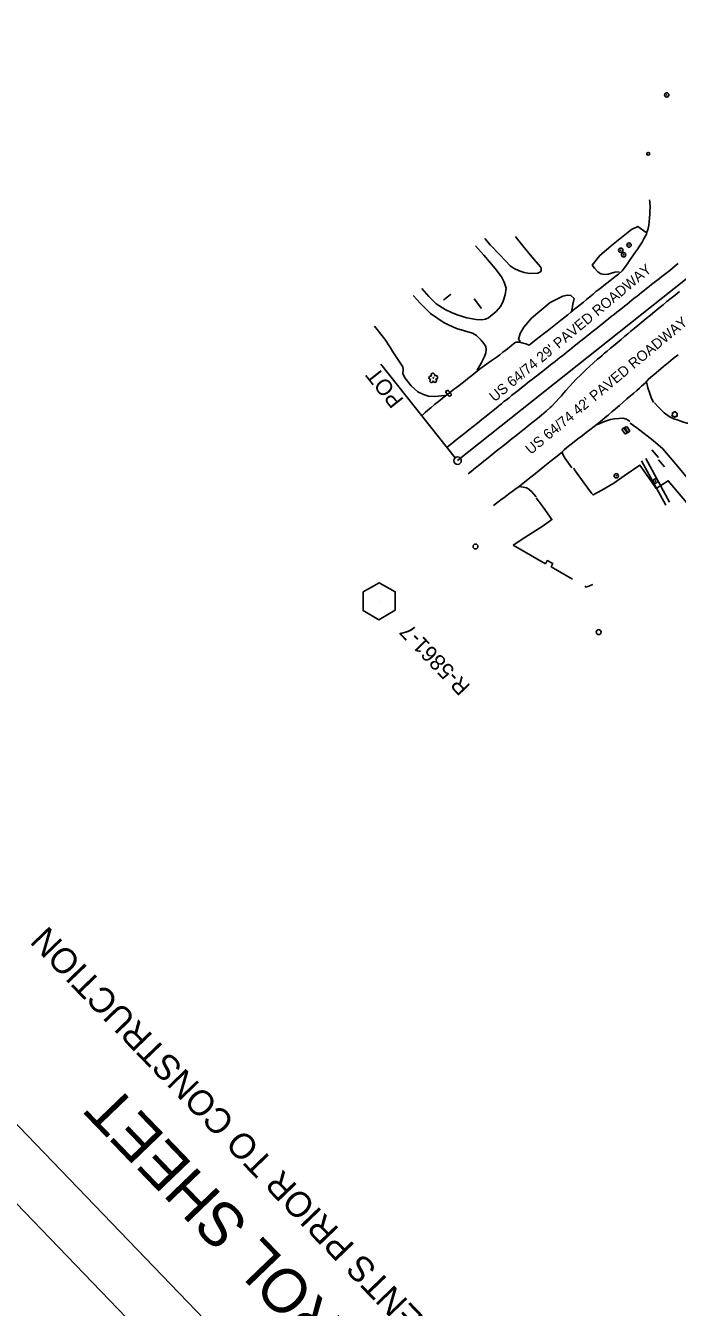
# Model space of a CAD drawing. Extents: x 471894 to 476235, y 503501 to 507878.
# Drawn here: x 472859 to 473516, y 505090 to 506381 of the extents above; entities that cross this region are included whole.
import ezdxf

# ---------------------------------------------------------------- set-up
doc = ezdxf.new("R2010")
doc.units = 0
for name, color, linetype in [('CTL Primary Horizontal and Vertical CELL', 7, 'Continuous'), ('CTL Primary Horizontal and Vertical Text', 7, 'Continuous'), ('CTL Sheet Border CELL', 7, 'Continuous'), ('Exist Horizontal Alignment', 7, 'Continuous'), ('Exist Other Culture Area Outline', 7, 'Continuous'), ('Exist Other Culture Gas Pump or Vent CELL', 7, 'Continuous'), ('Exist Other Culture Sign', 7, 'Continuous'), ('Exist Other Culture Sign Post CELL', 7, 'Continuous'), ('Exist Roads Curbs', 7, 'Continuous'), ('Exist Roads EOP', 7, 'Continuous'), ('Exist Roads EOP Other', 7, 'Continuous'), ('Exist Roads EOP Text', 7, 'Continuous'), ('Exist Utilities Other Located Object CELL', 7, 'Continuous'), ('Exist Utilities Other Pole CELL', 7, 'Continuous'), ('Exist Utilities Water Meter CELL', 7, 'Continuous'), ('Exist Vegetation Shrub CELL', 7, 'Continuous'), ('Exist Vegetation Tree CELL', 7, 'Continuous'), ('Sheet Plot Border Outside CELL', 7, 'Continuous')]:
    doc.layers.add(name, color=color, linetype=linetype)

msp = doc.modelspace()

# ---------------------------------------------------------------- linework, layer by layer
at = {"layer": 'CTL Primary Horizontal and Vertical CELL'}
msp.add_line((473215.4, 505801.6), (473215.4, 505801.6), dxfattribs=at)
msp.add_lwpolyline([(473199.3, 505811), (473215.5, 505820), (473231.8, 505811.1), (473231.5, 505792.5), (473215.3, 505783), (473199.3, 505792.1)], close=True, dxfattribs=at)
at = {"layer": 'CTL Sheet Border CELL'}
msp.add_lwpolyline([(471960, 506200), (474263.4, 503806.2), (475939, 505418.6), (473635.6, 507812.3)], close=True, dxfattribs=at)
at = {"layer": 'Exist Horizontal Alignment'}
for p, q in [((473294.5, 505943.2), (474190.9, 506656.2)), ((473292.2, 505946.1), (473217.2, 506040.5))]:
    msp.add_line(p, q, dxfattribs=at)
msp.add_circle((473294.5, 505943.2), 3.75, dxfattribs=at)
at = {"layer": 'Exist Other Culture Area Outline'}
for points in [[(473280.3, 506105.6), (473280.7, 506105.1), (473287.4, 506110.6), (473287.1, 506111)], [(473383.1, 505839.3), (473384.8, 505842.6), (473390.4, 505839.5), (473388.6, 505836.1)]]:
    msp.add_lwpolyline(points, dxfattribs=at)
at = {"layer": 'Exist Other Culture Gas Pump or Vent CELL'}
msp.add_circle((473486.6, 506252.2), 1.44, dxfattribs=at)
at = {"layer": 'Exist Other Culture Sign'}
for p, q in [((473318.7, 506096.5), (473311.3, 506106.3)), ((473484.1, 505945.4), (473508, 505901.5)), ((473496.8, 505946.2), (473490.1, 505954.2)), ((473504.1, 505898.3), (473479.8, 505942.9)), ((473502.8, 505937.1), (473496.9, 505943.9))]:
    msp.add_line(p, q, dxfattribs=at)
at = {"layer": 'Exist Other Culture Sign Post CELL'}
for centre, radius in [((473454.3, 505927.9), 2.18), ((473454.3, 505927.9), 0.24), ((473493.7, 505922.6), 2.18), ((473493.7, 505922.6), 0.24)]:
    msp.add_circle(centre, radius, dxfattribs=at)
at = {"layer": 'Exist Roads Curbs'}
for p, q in [((473383.1, 505839.3), (473350.5, 505858)), ((473410.3, 505823.7), (473388.6, 505836.1)), ((473423.9, 505815.9), (473422.5, 505816.7))]:
    msp.add_line(p, q, dxfattribs=at)
at = {"layer": 'Exist Roads EOP'}
for points in [[(473258.4, 505988.4), (473261.9, 505991.7), (473264.4, 505993.9), (473267.4, 505996.5), (473271.3, 505999.6), (473273.8, 506001.6), (473276.5, 506003.8), (473279.4, 506006.1), (473282.2, 506008.3), (473285, 506010.5), (473287.7, 506012.6), (473290.5, 506014.7), (473293.3, 506016.8), (473296.1, 506019), (473299, 506021.3), (473302, 506023.5), (473304.8, 506025.8), (473307.6, 506028), (473310.4, 506030.2), (473313, 506032.3), (473317.5, 506035.9), (473321.4, 506038.8), (473325.9, 506042), (473328.4, 506043.8), (473333.2, 506047.2), (473337, 506049.9), (473340.2, 506052.3), (473343.3, 506054.7), (473346.3, 506057.2), (473349.2, 506059.5), (473352.1, 506061.8), (473352.6, 506062.1), (473352.9, 506062.3), (473353.2, 506062.4), (473353.5, 506062.5), (473354.1, 506062.6), (473354.8, 506062.6), (473355.6, 506062.6), (473356.7, 506062.4), (473360.5, 506061.5), (473363.2, 506060.7), (473366.6, 506059.6), (473372, 506063.8), (473376.8, 506067.5), (473381, 506070.8), (473384.8, 506073.7), (473388.2, 506076.4), (473391.6, 506079), (473394.9, 506081.6), (473398.1, 506084.2), (473401.1, 506086.6), (473405.6, 506090.2), (473408.7, 506092.7), (473412.7, 506096), (473415.4, 506098.1), (473418.2, 506100.4), (473421.2, 506102.9), (473424.4, 506105.5), (473427.7, 506108.2), (473430.9, 506110.9), (473433.9, 506113.4), (473436.7, 506115.6), (473439.3, 506117.6), (473441.8, 506119.6), (473444.7, 506121.8), (473447.8, 506124.2), (473451.1, 506126.9), (473454.3, 506129.3), (473456.6, 506131.1), (473460, 506133.9), (473460.3, 506134.2), (473463.5, 506138.7), (473465.9, 506142.2), (473467.7, 506144.8), (473470.9, 506149.5), (473473.1, 506152.6), (473475.9, 506156.5), (473477.1, 506158.2), (473480.4, 506163.1), (473482.5, 506167.2), (473484.6, 506171.3), (473485.5, 506173.9), (473486.4, 506177), (473487, 506180.3), (473487.5, 506183.8), (473487.9, 506187.6), (473488.1, 506191.4), (473488.2, 506195), (473488.3, 506198.2), (473488, 506203.9), (473487.8, 506205.8)], [(473516.8, 506141.7), (473513.8, 506139.3), (473510.9, 506137), (473508.2, 506134.8), (473505.5, 506132.7), (473502.9, 506130.6), (473500.3, 506128.5), (473497.7, 506126.5), (473495.1, 506124.5), (473492.5, 506122.5), (473489.9, 506120.5), (473487.3, 506118.5), (473484.8, 506116.5), (473482.3, 506114.5), (473479.8, 506112.5), (473477.4, 506110.6), (473474.9, 506108.6), (473472.5, 506106.7), (473470.1, 506104.7), (473467.7, 506102.8), (473465.2, 506100.8), (473462.7, 506098.9), (473460.2, 506096.8), (473457.6, 506094.7), (473454.9, 506092.6), (473452.1, 506090.4), (473449.3, 506088.2), (473446.5, 506085.9), (473443.6, 506083.6), (473440.8, 506081.4), (473438, 506079.2), (473435.4, 506077.1), (473432.8, 506075), (473430.2, 506072.9), (473427.6, 506070.9), (473425.1, 506068.8), (473422.5, 506066.8), (473419.9, 506064.7), (473417.4, 506062.7), (473414.9, 506060.7), (473412.4, 506058.7), (473409.9, 506056.8), (473407.5, 506054.8), (473405, 506052.8), (473402.5, 506050.9), (473400.1, 506048.9), (473397.6, 506047), (473395.2, 506045.1), (473392.8, 506043.2), (473388.1, 506039.6), (473383.6, 506036), (473379, 506032.4), (473374.3, 506028.7), (473371.9, 506026.9), (473369.5, 506025), (473367.1, 506023.1), (473364.6, 506021.1), (473362.1, 506019.1), (473359.5, 506017.1), (473356.9, 506015), (473354.2, 506012.9), (473351.5, 506010.8), (473348.9, 506008.7), (473346.3, 506006.6), (473343.8, 506004.6), (473341.2, 506002.6), (473338.6, 506000.5), (473336, 505998.4), (473333.3, 505996.2), (473330.4, 505993.8), (473327, 505991.1), (473323.2, 505988), (473318.9, 505984.6), (473314.5, 505981.1), (473310.1, 505977.6), (473305.9, 505974.2), (473301.7, 505970.9), (473297.5, 505967.5), (473293.1, 505964.1), (473288.6, 505960.5), (473284, 505956.9), (473283.8, 505956.7)], [(473305.2, 505929.9), (473308.2, 505932.3), (473312.5, 505935.8), (473316.8, 505939.2), (473321.1, 505942.6), (473325.2, 505946), (473329.3, 505949.3), (473333.4, 505952.6), (473337.5, 505955.9), (473341.6, 505959.1), (473345.5, 505962.3), (473349.4, 505965.4), (473353.1, 505968.3), (473356.8, 505971.2), (473360.2, 505973.9), (473363.2, 505976.3), (473366, 505978.5), (473370.6, 505982.3), (473375, 505985.8), (473379, 505989.1), (473383.6, 505993), (473387.9, 505996.6), (473389.5, 505998.2), (473393.6, 506002.3), (473396.9, 506006), (473399, 506008.3), (473401.3, 506011.1), (473403.6, 506013.7), (473407.2, 506017.9), (473410.6, 506021.6), (473414.3, 506025.6), (473418.2, 506029.4), (473420.2, 506031.4), (473424.1, 506035), (473427.6, 506038.2), (473431.4, 506041.7), (473435.5, 506045.3), (473437.7, 506047.2), (473440, 506049.2), (473442.5, 506051.3), (473445.2, 506053.5), (473448.3, 506056.1), (473451.6, 506058.9), (473455.3, 506062), (473459.1, 506065.2), (473462.6, 506068.2), (473466, 506071), (473469.1, 506073.6), (473472.4, 506076.3), (473476, 506079.3), (473480, 506082.6), (473484.3, 506086.2), (473488.8, 506089.8), (473493.2, 506093.4), (473497.3, 506096.8), (473501.4, 506100.1), (473505.4, 506103.4), (473509.5, 506106.7), (473513.6, 506110), (473517.9, 506113.4)], [(473516.5, 506049.8), (473511.7, 506045.9), (473506.9, 506042), (473501.9, 506037.9), (473496.9, 506033.8), (473492.4, 506030), (473489.2, 506027.3), (473486.3, 506024.8), (473483.6, 506021.6), (473479.8, 506018.2), (473477.6, 506016.2), (473475, 506013.9), (473472, 506011.3), (473468.7, 506008.4), (473465.1, 506005.3), (473461.3, 506002), (473457.5, 505998.7), (473453.6, 505995.4), (473449.8, 505992.2), (473446.2, 505989.1), (473443.1, 505986.5), (473440.5, 505984.4), (473436.6, 505981.2), (473432, 505977.5), (473427.6, 505974.2), (473424.1, 505971.6), (473419.9, 505968.3), (473415.6, 505965), (473411.9, 505962.1), (473408.9, 505959.7), (473404.7, 505956.3), (473401.9, 505954), (473398.7, 505951.2), (473394.7, 505947.8), (473392.1, 505945.6), (473389.2, 505943.2), (473385.9, 505940.6), (473382.4, 505937.8), (473378.7, 505934.8), (473375, 505931.8), (473371.2, 505928.8), (473367.3, 505925.8), (473363.7, 505923), (473360.7, 505920.6), (473356.4, 505917.3), (473352.2, 505914.2), (473349.4, 505912.1), (473346, 505909.7), (473342.3, 505906.9), (473338.2, 505903.8), (473333.8, 505900.5), (473330.7, 505898)]]:
    msp.add_lwpolyline(points, dxfattribs=at)
at = {"layer": 'Exist Roads EOP Other'}
for points in [[(473484.5, 506172.9), (473475.9, 506179), (473469.8, 506176.1), (473451.2, 506161.1), (473437.7, 506149.8), (473429.9, 506139.9)], [(473321.9, 506167), (473327.4, 506160.7), (473337.1, 506150.5), (473342.7, 506144.3), (473347.6, 506139.3), (473351.5, 506136.8), (473356.4, 506134.2), (473361.7, 506132.6), (473367.1, 506131.8), (473375.2, 506131.9), (473378, 506133.2), (473378.8, 506134.2), (473378.7, 506136.9), (473378.1, 506138.3), (473375.7, 506141)], [(473375.7, 506141), (473369.2, 506148.6), (473360.3, 506159.5), (473353.5, 506168), (473352.8, 506168.8)], [(473258.5, 506116.4), (473265.4, 506108.5), (473272.9, 506101.2), (473281.9, 506095.4), (473289, 506092), (473295.2, 506089.6), (473303.8, 506087), (473313.1, 506085.4), (473318.8, 506085), (473322.5, 506085.6), (473325.7, 506087.1), (473333.2, 506093.3), (473338, 506098.7), (473340.4, 506103.8), (473342.3, 506110.3), (473343.4, 506116.8), (473341.5, 506122.9), (473338.6, 506128.3), (473332.3, 506136.8), (473321.1, 506150), (473312.4, 506159.4)], [(473457.3, 506133.2), (473452.8, 506133), (473446.2, 506131), (473442.2, 506130.6), (473438.7, 506131.5), (473435.6, 506133.5), (473432.3, 506137), (473429.9, 506139.9)], [(473314.2, 506034.4), (473318.1, 506041.2), (473321.5, 506048), (473323, 506051.8), (473323.2, 506055.1), (473322.8, 506058.2), (473321, 506061.2), (473317.8, 506064.9), (473313.6, 506069.2), (473309.6, 506071.6), (473293.3, 506076.3), (473280.9, 506082), (473267.3, 506091.3), (473257.2, 506101.3), (473249.9, 506109.6)], [(473411.9, 506106.4), (473408.6, 506109.6), (473405.1, 506109.9), (473400.4, 506109), (473387.9, 506102.4), (473369.1, 506086.6), (473361.3, 506077.5), (473357.5, 506071.3), (473356, 506065.7)], [(473409.6, 506094.3), (473410.5, 506100.9), (473411.9, 506106.4)], [(473281.6, 506008.7), (473271.6, 506007.8), (473265.2, 506008.2), (473260.1, 506009.7), (473254.5, 506012.4), (473247.6, 506018.7), (473241.4, 506026.6), (473239.5, 506030.8), (473239.6, 506034.6), (473239.5, 506037.6), (473234.6, 506044.7), (473229.2, 506052.8), (473227, 506056.9), (473221.2, 506065.7), (473210.9, 506078.5)], [(473356, 506065.7), (473357.4, 506063.2)], [(473493.1, 506001.4), (473493.3, 506001.2), (473496.3, 505997.8), (473502.7, 505991.4), (473507.7, 505987.8), (473512.2, 505985.4), (473516.7, 505983.8), (473521.9, 505982.1), (473525.8, 505981.1), (473530.2, 505981), (473534.2, 505981.9), (473535.9, 505982.6), (473546.8, 505989.6), (473558.4, 505998), (473566.4, 506004.6), (473571, 506011.3), (473573, 506016.4), (473574, 506021.4), (473573.7, 506027.3), (473572.1, 506032.3), (473569.7, 506037.2), (473564.6, 506046.6), (473560.2, 506053.6), (473559.7, 506054.2)], [(473314, 506034.2), (473314.2, 506034.4)], [(473484.9, 506022.3), (473485.3, 506019.5), (473486, 506016.6), (473487.7, 506011.9), (473489.6, 506006.9), (473491.9, 506001.7)], [(473435.5, 505979.7), (473442.4, 505982.7), (473448.5, 505984.5), (473452.6, 505985.2), (473456.9, 505985.8), (473461, 505986), (473464.5, 505984.9), (473467.7, 505983), (473468.1, 505982.7)], [(473601.7, 505924.1), (473601, 505923.2), (473591.5, 505915.5), (473581.7, 505907.5), (473580.1, 505906.7), (473569, 505906.6), (473563.6, 505906), (473550.7, 505894.9), (473542.8, 505904.8), (473530.4, 505920.3), (473518, 505935.3), (473501.3, 505955.1), (473491.5, 505963.4), (473474.9, 505976.4), (473468.3, 505980.8), (473468.2, 505980.9)], [(473399.8, 505951.6), (473400.9, 505948.8), (473402.7, 505945.5), (473409.7, 505935.8)], [(473411.5, 505935.5), (473412.4, 505934.1), (473422.1, 505920.6), (473429.3, 505910.5), (473430.9, 505908.6), (473439.9, 505913.6), (473451.8, 505920.6), (473462.3, 505927.8), (473478.2, 505938.6), (473489.6, 505922.5), (473494.4, 505915.3), (473506.6, 505923), (473525.5, 505900.6), (473534.2, 505890.5), (473536.1, 505892.1), (473537.5, 505893.2)], [(473350.5, 505858), (473362.2, 505865.9), (473380.8, 505877.7), (473389.5, 505883.8), (473380.6, 505896.3), (473373.7, 505905.9)], [(473356.5, 505917.1), (473360.5, 505916.6), (473363.9, 505915.8), (473366.2, 505914.6), (473369.1, 505912.1), (473373.5, 505906.9)], [(473430.8, 505818.3), (473423.9, 505815.9)]]:
    msp.add_lwpolyline(points, dxfattribs=at)
at = {"layer": 'Exist Utilities Other Located Object CELL'}
for centre, radius in [((473505.2, 506311.5), 2.18), ((473505.2, 506311.5), 0.24), ((473458.9, 506155.1), 2.18), ((473458.9, 506155.1), 0.24), ((473461.7, 506150.5), 2.18), ((473461.7, 506150.5), 0.24), ((473467.2, 506160.3), 2.18), ((473467.2, 506160.3), 0.24)]:
    msp.add_circle(centre, radius, dxfattribs=at)
at = {"layer": 'Exist Utilities Other Pole CELL'}
for centre in [(473312.5, 505856.7), (473436.6, 505770.5)]:
    msp.add_circle(centre, 2.46, dxfattribs=at)
at = {"layer": 'Exist Utilities Water Meter CELL'}
for p, q in [((473285.4, 506011), (473285.4, 506011)), ((473462.9, 505973.3), (473462.9, 505973.3)), ((473465.1, 505974.4), (473465.1, 505974.4))]:
    msp.add_line(p, q, dxfattribs=at)
for points in [[(473285.5, 506008.3), (473282.8, 506011.4)], [(473285.6, 506008.4), (473282.9, 506011.5)], [(473285.3, 506013.6), (473288, 506010.5)], [(473285.4, 506013.6), (473288.1, 506010.6)], [(473462.5, 505970.7), (473460.3, 505974.1)], [(473462.6, 505970.7), (473460.4, 505974.2)], [(473464.8, 505971.8), (473462.5, 505975.2)], [(473464.9, 505971.9), (473462.6, 505975.3)], [(473463.1, 505975.9), (473465.3, 505972.4)], [(473463.2, 505975.9), (473465.4, 505972.5)], [(473465.2, 505977), (473467.5, 505973.6)], [(473465.4, 505977.1), (473467.6, 505973.7)]]:
    msp.add_lwpolyline(points, dxfattribs=at)
for centre, radius, start, end in [((473284.6, 506012), 1.86, 64.3796, 197.181), ((473284.6, 506012), 1.73, 66.5025, 194.9839), ((473286.3, 506010), 1.86, 244.8499, 17.51), ((473286.3, 506010), 1.73, 246.3288, 16.0744), ((473462.2, 505974.4), 1.86, 55.7823, 188.5836), ((473462.2, 505974.4), 1.73, 57.9052, 186.3866), ((473464.3, 505975.5), 1.86, 56.7324, 189.5337), ((473463.6, 505972.2), 1.86, 236.2525, 8.9126), ((473464.4, 505975.5), 1.73, 58.8553, 187.3367), ((473463.6, 505972.2), 1.73, 237.7314, 7.4771), ((473465.8, 505973.3), 1.86, 237.2027, 9.8627), ((473465.8, 505973.3), 1.73, 238.6815, 8.4272)]:
    msp.add_arc(centre, radius, start, end, dxfattribs=at)
at = {"layer": 'Exist Vegetation Shrub CELL'}
msp.add_line((473513.1, 505989.6), (473513.1, 505989.6), dxfattribs=at)
for centre, radius, start, end in [((473511.3, 505988.8), 0.955, 95.1099, 327.9534), ((473511.7, 505990.7), 0.968, 35.8908, 245.4216), ((473513, 505987.9), 0.984, 151.2797, 21.387), ((473513.4, 505991.6), 0.99, 334.8391, 200.4717), ((473514.8, 505988.6), 0.937, 204.9913, 73.4601), ((473514.8, 505990.4), 0.929, 284.4567, 126.0861)]:
    msp.add_arc(centre, radius, start, end, dxfattribs=at)
at = {"layer": 'Exist Vegetation Tree CELL'}
msp.add_line((473270, 506026.6), (473270, 506026.6), dxfattribs=at)
msp.add_circle((473270, 506026.6), 0.326, dxfattribs=at)
for centre, radius, start, end in [((473267.4, 506026.7), 1.73, 62.6636, 279.3457), ((473268.3, 506023.4), 1.69, 111.5671, 6.231), ((473269.6, 506029.4), 1.86, 330.1651, 219.7134), ((473271.7, 506023.7), 1.7, 181.2822, 74.56), ((473272.6, 506027.1), 1.9, 257.1011, 134.1999)]:
    msp.add_arc(centre, radius, start, end, dxfattribs=at)
at = {"layer": 'Sheet Plot Border Outside CELL'}
msp.add_lwpolyline([(476235.3, 505190.5), (473649.4, 507877.9), (471894, 506188.7), (474479.9, 503501.3)], close=True, dxfattribs=at)

# ---------------------------------------------------------------- texts
at = {"layer": 'CTL Primary Horizontal and Vertical Text'}
msp.add_text('R-5861-7', height=16, rotation=133.8986, dxfattribs=at).set_placement((473308.2, 505716.3))
at = {"layer": 'CTL Sheet Border CELL'}
for s, height, p in [('W/  EXISTING CENTERLINE ALIGNMENTS PRIOR TO CONSTRUCTION', 25.469, (473667, 504659)), ('SURVEY CONTROL SHEET ', 44.294, (473478.3, 504767))]:
    msp.add_text(s, height=height, rotation=133.8985, dxfattribs=at).set_placement(p)
at = {"layer": 'Exist Horizontal Alignment'}
msp.add_text('POT', height=16, rotation=128.4983, dxfattribs=at).set_placement((473240.9, 506004.4))
at = {"layer": 'Exist Roads EOP Text'}
for s, p in [("US 64/74 29' PAVED ROADWAY", (473331.8, 506001.9)), ("US 64/74 42' PAVED ROADWAY", (473368.2, 505948.8))]:
    msp.add_text(s, height=10.4, rotation=39.7704, dxfattribs=at).set_placement(p)

doc.saveas('drawing.dxf')
